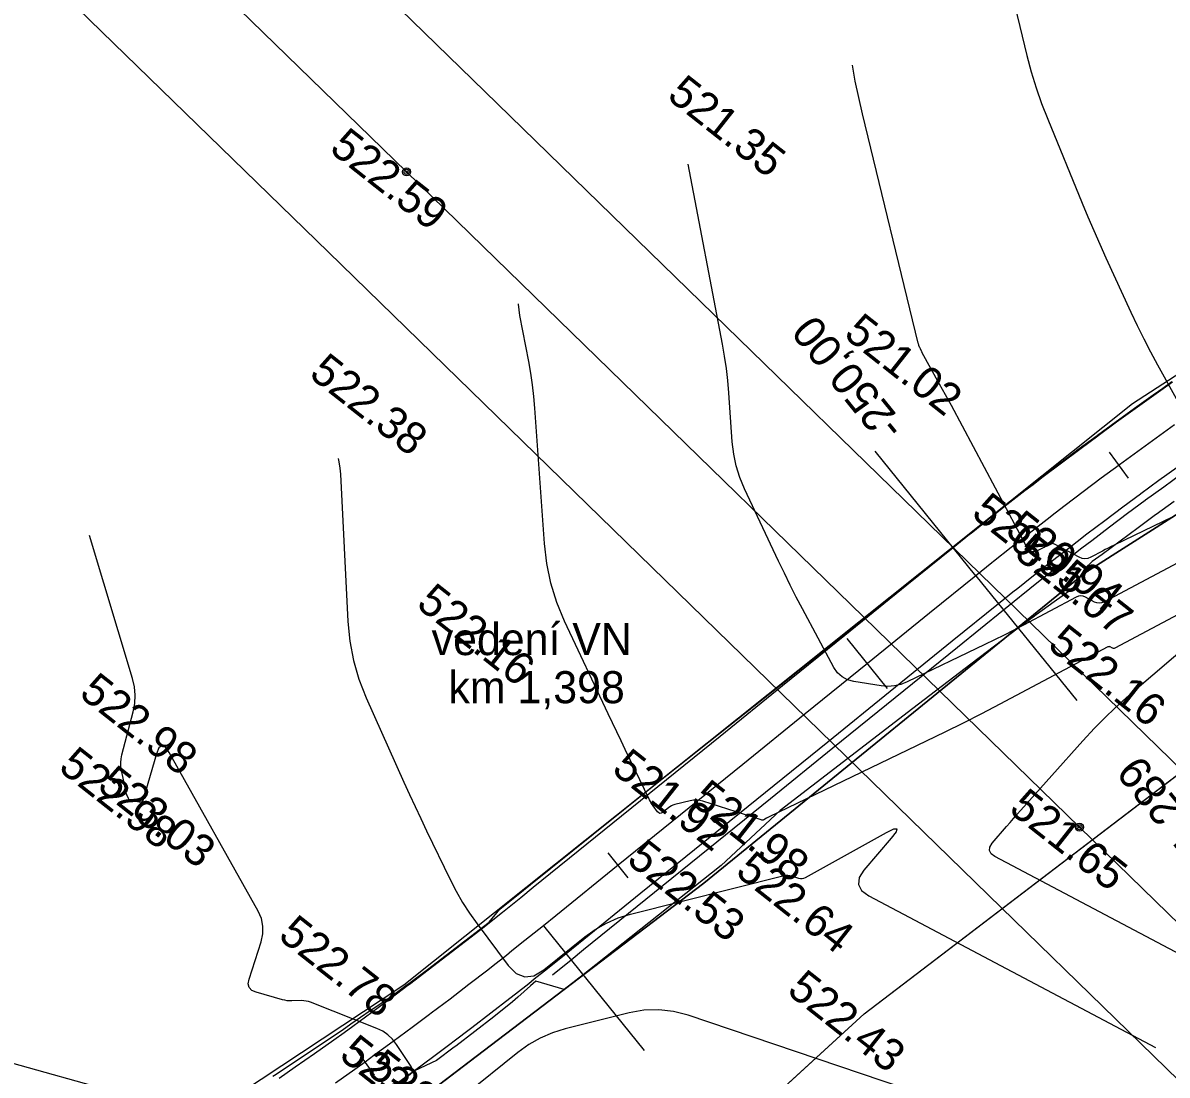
# Model space of a CAD drawing. Extents: x -636600 to -628587, y -1090963 to -1085869.
# Drawn here: x -629735.5 to -629664.1, y -1089734.5 to -1089668.9 of the extents above; entities that cross this region are included whole.
import ezdxf

# ---------------------------------------------------------------- set-up
doc = ezdxf.new("R2010")
doc.units = 0
for name, color, linetype in [('01_PARCELY_NÁVRH_PC', 7, 'Continuous'), ('07_OCH_P A POPISY TI', 7, 'Continuous'), ('21', 7, 'Continuous'), ('33', 7, 'Continuous'), ('34', 7, 'Continuous'), ('dno příkopu', 7, 'Continuous'), ('Ex_Major Contours', 7, 'Continuous'), ('Ex_Minor Contours', 7, 'Continuous'), ('HEKTOMETRY100', 7, 'Continuous'), ('HEKTOMETRY20', 7, 'Continuous'), ('HL_BODY', 7, 'Continuous'), ('koty_vše', 7, 'Continuous'), ('PARCELY_NÁVRH_SILNICE_ŽELEZNICE', 7, 'Continuous'), ('POLOMERY', 7, 'Continuous'), ('popis', 7, 'Continuous'), ('situace_osa', 7, 'Continuous'), ('situace_těleso', 7, 'Continuous'), ('situace_vozovka', 7, 'Continuous')]:
    doc.layers.add(name, color=color, linetype=linetype)

msp = doc.modelspace()

# ---------------------------------------------------------------- linework, layer by layer
at = {"layer": '01_PARCELY_NÁVRH_PC'}
msp.add_lwpolyline([(-629647.363, -1089680.417), (-629666.288, -1089692.668), (-629711.76, -1089728.929), (-629739.767, -1089747.431), (-629770.066, -1089766.37), (-629781.624, -1089778.209), (-629800.275, -1089807.802), (-629798.048, -1089809.483), (-629791.307, -1089814.356), (-629789.014, -1089815.993), (-629775.661, -1089789.328), (-629773.774, -1089778.258), (-629755.349, -1089764.02), (-629715.944, -1089740.02), (-629693.039, -1089722.565), (-629669.229, -1089703.189), (-629636.498, -1089682.368)], dxfattribs=at)
at = {"layer": '07_OCH_P A POPISY TI'}
for points in [[(-629808.416, -1089574.342), (-629758.17, -1089623.152), (-629706.697, -1089673.191), (-629664.708, -1089714.065), (-629606.854, -1089770.374), (-629556.972, -1089818.979), (-629519.085, -1089855.932)], [(-629812.884, -1089589.521), (-629767.926, -1089633.192), (-629716.459, -1089683.226), (-629674.473, -1089724.097), (-629616.621, -1089780.404), (-629566.745, -1089829.004), (-629539.136, -1089855.932)]]:
    msp.add_lwpolyline(points, dxfattribs=at)
at = {"layer": '21'}
for p, q in [((-629636.498, -1089682.368), (-629669.229, -1089703.189)), ((-629669.229, -1089703.189), (-629693.039, -1089722.565)), ((-629683.036, -1089730.713), (-629659.95, -1089713.109)), ((-629693.039, -1089722.565), (-629715.944, -1089740.02)), ((-629704.711, -1089750.564), (-629683.036, -1089730.713))]:
    msp.add_line(p, q, dxfattribs=at)
at = {"layer": '33'}
for centre, radius in [((-629711.578, -1089678.208), 0.25), ((-629711.578, -1089678.208), 0.158), ((-629711.578, -1089678.208), 0.05), ((-629669.591, -1089719.081), 0.25), ((-629669.591, -1089719.081), 0.158), ((-629669.591, -1089719.081), 0.05)]:
    msp.add_circle(centre, radius, dxfattribs=at)
at = {"layer": '34'}
for p, q in [((-629763.048, -1089628.172), (-629711.578, -1089678.208)), ((-629711.578, -1089678.208), (-629669.591, -1089719.081)), ((-629669.591, -1089719.081), (-629611.696, -1089775.422))]:
    msp.add_line(p, q, dxfattribs=at)
at = {"layer": 'dno příkopu'}
msp.add_lwpolyline([(-629663.207, -1089697.045), (-629664.34, -1089697.865), (-629665.469, -1089698.692), (-629665.493, -1089698.71), (-629666.593, -1089699.525), (-629667.713, -1089700.365), (-629668.828, -1089701.211), (-629669.444, -1089701.683), (-629669.938, -1089702.063), (-629671.043, -1089702.921), (-629672.143, -1089703.786), (-629673.238, -1089704.657), (-629673.335, -1089704.734), (-629674.329, -1089705.534), (-629677.213, -1089707.868), (-629681.101, -1089711.012), (-629684.988, -1089714.157), (-629688.875, -1089717.302), (-629692.762, -1089720.447), (-629696.649, -1089723.592), (-629700.536, -1089726.737), (-629701.31, -1089727.363), (-629702.477, -1089728.301)], dxfattribs=at)
at = {"layer": 'Ex_Major Contours'}
msp.add_lwpolyline([(-629715.841, -1089696.08), (-629715.797, -1089696.291), (-629715.742, -1089696.678), (-629715.711, -1089697.068), (-629715.247, -1089706.26), (-629715.129, -1089707.486), (-629714.899, -1089708.685), (-629714.559, -1089709.856), (-629714.107, -1089711.002), (-629711.745, -1089716.269), (-629711.401, -1089717.03), (-629711.051, -1089717.788), (-629710.696, -1089718.543), (-629710.335, -1089719.296), (-629708.858, -1089722.349), (-629708.49, -1089723.067), (-629708.088, -1089723.766), (-629707.653, -1089724.444), (-629707.186, -1089725.102), (-629705.25, -1089727.696), (-629704.748, -1089728.2), (-629704.209, -1089728.415), (-629703.633, -1089728.341), (-629703.021, -1089727.978), (-629700.465, -1089725.922), (-629699.81, -1089725.45), (-629699.115, -1089725.055), (-629698.382, -1089724.74), (-629697.609, -1089724.502), (-629688.012, -1089722.099), (-629687.9, -1089722.079), (-629687.787, -1089722.074), (-629687.675, -1089722.086), (-629687.564, -1089722.114), (-629687.12, -1089722.258), (-629687.01, -1089722.282), (-629686.903, -1089722.283), (-629686.797, -1089722.261), (-629686.694, -1089722.216), (-629681.626, -1089719.408), (-629681.179, -1089719.192), (-629680.981, -1089719.18), (-629681.032, -1089719.372), (-629681.334, -1089719.767), (-629683.04, -1089721.754), (-629683.341, -1089722.227), (-629683.39, -1089722.652), (-629683.188, -1089723.029), (-629682.735, -1089723.359), (-629664.849, -1089732.81)], dxfattribs=at)
at = {"layer": 'Ex_Minor Contours'}
for points in [[(-629674.115, -1089665.758), (-629673.921, -1089666.628), (-629672.869, -1089670.954), (-629672.603, -1089671.966), (-629672.299, -1089672.966), (-629671.956, -1089673.954), (-629671.576, -1089674.929), (-629669.424, -1089680.154), (-629669.066, -1089681.012), (-629668.699, -1089681.866), (-629668.324, -1089682.717), (-629667.941, -1089683.564), (-629666.385, -1089686.956), (-629665.993, -1089687.791), (-629665.584, -1089688.618), (-629665.159, -1089689.437), (-629664.719, -1089690.248), (-629662.183, -1089694.81)], [(-629650.979, -1089693.544), (-629667.431, -1089701.486), (-629667.616, -1089701.576), (-629667.799, -1089701.668), (-629667.982, -1089701.761), (-629668.164, -1089701.857), (-629668.89, -1089702.242), (-629669.071, -1089702.314), (-629669.252, -1089702.338), (-629669.434, -1089702.314), (-629669.615, -1089702.242), (-629671.154, -1089701.421), (-629671.212, -1089701.398), (-629671.27, -1089701.39), (-629671.328, -1089701.397), (-629671.386, -1089701.42), (-629671.619, -1089701.544), (-629671.677, -1089701.574), (-629671.736, -1089701.604), (-629671.795, -1089701.634), (-629671.854, -1089701.662), (-629672.326, -1089701.889), (-629672.365, -1089701.904), (-629672.404, -1089701.913), (-629672.444, -1089701.916), (-629672.485, -1089701.913), (-629672.65, -1089701.887), (-629672.689, -1089701.877), (-629672.722, -1089701.859), (-629672.75, -1089701.834), (-629672.773, -1089701.801), (-629677.589, -1089692.781), (-629677.769, -1089692.446), (-629677.95, -1089692.111), (-629678.133, -1089691.777), (-629678.318, -1089691.443), (-629679.4, -1089689.496), (-629679.414, -1089689.471), (-629679.427, -1089689.445), (-629679.44, -1089689.419), (-629679.452, -1089689.393), (-629679.5, -1089689.289), (-629679.512, -1089689.262), (-629679.523, -1089689.236), (-629679.535, -1089689.209), (-629679.546, -1089689.183), (-629679.609, -1089689.03), (-629679.623, -1089688.995), (-629679.635, -1089688.96), (-629679.646, -1089688.924), (-629679.655, -1089688.888), (-629683.132, -1089674.583), (-629683.582, -1089672.561), (-629683.765, -1089671.56)], [(-629656.845, -1089699.077), (-629668.072, -1089705.039), (-629668.216, -1089705.096), (-629668.36, -1089705.115), (-629668.504, -1089705.096), (-629668.647, -1089705.038), (-629669.222, -1089704.732), (-629669.366, -1089704.674), (-629669.51, -1089704.655), (-629669.653, -1089704.674), (-629669.797, -1089704.731), (-629673.092, -1089706.475), (-629673.691, -1089706.788), (-629674.292, -1089707.095), (-629674.897, -1089707.396), (-629675.504, -1089707.692), (-629680.348, -1089710.02), (-629680.74, -1089710.175), (-629681.142, -1089710.267), (-629681.553, -1089710.296), (-629681.973, -1089710.262), (-629683.673, -1089709.999), (-629684.07, -1089709.895), (-629684.411, -1089709.712), (-629684.697, -1089709.45), (-629684.927, -1089709.11), (-629686.875, -1089705.463), (-629687.262, -1089704.727), (-629687.64, -1089703.985), (-629688.009, -1089703.239), (-629688.368, -1089702.489), (-629690.498, -1089697.968), (-629690.79, -1089697.265), (-629691.015, -1089696.545), (-629691.171, -1089695.807), (-629691.259, -1089695.051), (-629691.474, -1089691.99), (-629691.539, -1089691.227), (-629691.627, -1089690.466), (-629691.737, -1089689.709), (-629691.87, -1089688.954), (-629694.019, -1089677.725)], [(-629658.821, -1089703.357), (-629667.397, -1089707.911), (-629667.433, -1089707.925), (-629667.468, -1089707.929), (-629667.503, -1089707.924), (-629667.538, -1089707.91), (-629667.679, -1089707.835), (-629667.714, -1089707.821), (-629667.749, -1089707.817), (-629667.784, -1089707.821), (-629667.819, -1089707.835), (-629674.565, -1089711.406), (-629675.704, -1089712.001), (-629676.848, -1089712.586), (-629677.998, -1089713.159), (-629679.154, -1089713.722), (-629688.954, -1089718.432), (-629688.997, -1089718.453), (-629689.039, -1089718.475), (-629689.082, -1089718.497), (-629689.124, -1089718.52), (-629689.291, -1089718.612), (-629689.333, -1089718.631), (-629689.376, -1089718.64), (-629689.42, -1089718.639), (-629689.465, -1089718.629), (-629693.089, -1089717.457), (-629693.285, -1089717.408), (-629693.481, -1089717.387), (-629693.679, -1089717.394), (-629693.877, -1089717.43), (-629694.849, -1089717.674), (-629694.957, -1089717.707), (-629695.059, -1089717.751), (-629695.156, -1089717.806), (-629695.247, -1089717.871), (-629695.603, -1089718.158), (-629695.689, -1089718.209), (-629695.769, -1089718.219), (-629695.844, -1089718.189), (-629695.914, -1089718.119), (-629696.184, -1089717.757), (-629696.249, -1089717.665), (-629696.31, -1089717.571), (-629696.366, -1089717.474), (-629696.417, -1089717.373), (-629697.933, -1089714.239), (-629698.201, -1089713.683), (-629698.468, -1089713.126), (-629698.733, -1089712.568), (-629698.997, -1089712.009), (-629701.722, -1089706.225), (-629702.207, -1089705.06), (-629702.579, -1089703.865), (-629702.838, -1089702.641), (-629702.984, -1089701.388), (-629703.579, -1089692.942), (-629703.641, -1089692.213), (-629703.724, -1089691.487), (-629703.83, -1089690.764), (-629703.956, -1089690.044), (-629704.507, -1089687.169), (-629704.599, -1089686.453), (-629704.599, -1089686.445)], [(-629711.09, -1089734.688), (-629711.128, -1089734.356), (-629711.294, -1089734.014), (-629712.208, -1089732.626), (-629712.457, -1089732.304), (-629712.745, -1089732.03), (-629713.072, -1089731.804), (-629713.439, -1089731.628), (-629717.568, -1089730), (-629717.707, -1089729.952), (-629717.849, -1089729.92), (-629717.993, -1089729.902), (-629718.14, -1089729.898), (-629718.732, -1089729.913), (-629718.879, -1089729.912), (-629719.025, -1089729.899), (-629719.17, -1089729.875), (-629719.313, -1089729.841), (-629720.965, -1089729.377), (-629721.234, -1089729.258), (-629721.397, -1089729.082), (-629721.454, -1089728.848), (-629721.405, -1089728.558), (-629720.653, -1089726.223), (-629720.546, -1089725.732), (-629720.541, -1089725.252), (-629720.641, -1089724.783), (-629720.843, -1089724.323), (-629726.388, -1089714.421), (-629726.631, -1089714.082), (-629726.846, -1089713.985), (-629727.033, -1089714.129), (-629727.193, -1089714.514), (-629728.007, -1089717.349), (-629728.045, -1089717.434), (-629728.101, -1089717.489), (-629728.176, -1089717.515), (-629728.269, -1089717.511), (-629728.762, -1089717.42), (-629728.818, -1089717.403), (-629728.865, -1089717.375), (-629728.903, -1089717.337), (-629728.932, -1089717.287), (-629729.032, -1089717.065), (-629729.056, -1089717.009), (-629729.076, -1089716.952), (-629729.093, -1089716.893), (-629729.107, -1089716.834), (-629729.375, -1089715.519), (-629729.41, -1089715.28), (-629729.417, -1089715.043), (-629729.396, -1089714.806), (-629729.348, -1089714.569), (-629728.635, -1089711.887), (-629728.533, -1089711.363), (-629728.505, -1089710.839), (-629728.551, -1089710.317), (-629728.672, -1089709.796), (-629731.374, -1089700.882)], [(-629663.269, -1089727.043), (-629674.878, -1089720.908), (-629675.114, -1089720.737), (-629675.219, -1089720.541), (-629675.193, -1089720.32), (-629675.037, -1089720.074), (-629674.15, -1089719.042), (-629673.928, -1089718.784), (-629673.704, -1089718.528), (-629673.48, -1089718.272), (-629673.253, -1089718.018), (-629669.383, -1089713.692), (-629668.65, -1089712.899), (-629667.891, -1089712.133), (-629667.107, -1089711.392), (-629666.298, -1089710.677), (-629658.42, -1089703.946)], [(-629672.444, -1089738.109), (-629694, -1089730.812), (-629694.917, -1089730.571), (-629695.839, -1089730.465), (-629696.767, -1089730.496), (-629697.7, -1089730.662), (-629701.681, -1089731.659), (-629702.479, -1089731.904), (-629703.236, -1089732.23), (-629703.953, -1089732.637), (-629704.63, -1089733.125), (-629707.951, -1089735.797)], [(-629736.748, -1089733.625), (-629729.613, -1089735.629)]]:
    msp.add_lwpolyline(points, dxfattribs=at)
at = {"layer": 'HEKTOMETRY100'}
msp.add_lwpolyline([(-629681.572, -1089710.429), (-629684.088, -1089707.32)], dxfattribs=at)
at = {"layer": 'HEKTOMETRY20'}
for points in [[(-629666.531, -1089697.301), (-629667.717, -1089695.691)], [(-629697.75, -1089722.231), (-629699.008, -1089720.676)], [(-629713.584, -1089734.535), (-629714.753, -1089732.912)]]:
    msp.add_lwpolyline(points, dxfattribs=at)
at = {"layer": 'HL_BODY'}
for points in [[(-629676.058, -1089703.396), (-629669.769, -1089711.17)], [(-629703.04, -1089725.225), (-629696.75, -1089732.999)]]:
    msp.add_lwpolyline(points, dxfattribs=at)
at = {"layer": 'PARCELY_NÁVRH_SILNICE_ŽELEZNICE'}
msp.add_lwpolyline([(-629636.498, -1089682.368), (-629669.229, -1089703.189), (-629693.039, -1089722.565), (-629715.944, -1089740.02), (-629755.349, -1089764.02), (-629773.774, -1089778.258), (-629775.661, -1089789.328), (-629789.014, -1089815.993), (-629763.271, -1089834.375), (-629762.496, -1089834.892), (-629746.798, -1089807.362), (-629739.641, -1089797.354), (-629724.72, -1089773.793), (-629704.711, -1089750.564), (-629683.036, -1089730.713), (-629659.95, -1089713.109)], dxfattribs=at)
at = {"layer": 'POLOMERY'}
for points in [[(-629676.058, -1089703.396), (-629682.348, -1089695.621)], [(-629703.04, -1089725.225), (-629696.75, -1089732.999)]]:
    msp.add_lwpolyline(points, dxfattribs=at)
at = {"layer": 'situace_osa'}
msp.add_lwpolyline([(-629663.662, -1089693.99), (-629664.812, -1089694.813), (-629665.959, -1089695.642), (-629667.1, -1089696.478), (-629667.124, -1089696.496), (-629668.237, -1089697.32), (-629669.369, -1089698.169), (-629670.496, -1089699.025), (-629671.119, -1089699.502), (-629671.618, -1089699.886), (-629672.736, -1089700.754), (-629673.848, -1089701.628), (-629674.956, -1089702.509), (-629675.054, -1089702.587), (-629676.058, -1089703.396), (-629678.943, -1089705.73), (-629682.83, -1089708.874), (-629686.717, -1089712.019), (-629690.605, -1089715.164), (-629694.492, -1089718.309), (-629698.379, -1089721.454), (-629702.266, -1089724.599), (-629703.04, -1089725.225), (-629704.194, -1089726.152), (-629705.006, -1089726.799), (-629705.353, -1089727.073), (-629706.173, -1089727.718), (-629706.518, -1089727.987), (-629707.688, -1089728.894), (-629708.863, -1089729.795), (-629710.044, -1089730.688), (-629710.141, -1089730.761), (-629711.23, -1089731.574), (-629712.421, -1089732.453), (-629713.617, -1089733.325), (-629714.169, -1089733.724), (-629714.819, -1089734.19), (-629716.025, -1089735.048)], dxfattribs=at)
at = {"layer": 'situace_těleso'}
for points in [[(-629719.926, -1089734.605), (-629719.725, -1089734.475), (-629718.699, -1089733.802), (-629717.478, -1089732.992), (-629716.261, -1089732.174), (-629715.606, -1089731.728), (-629715.049, -1089731.348), (-629713.842, -1089730.515), (-629712.621, -1089729.701), (-629711.54, -1089728.898), (-629711.443, -1089728.826), (-629710.27, -1089727.946), (-629709.102, -1089727.059), (-629707.939, -1089726.165), (-629707.597, -1089725.9), (-629706.781, -1089725.264), (-629706.436, -1089724.994), (-629705.769, -1089724.182), (-629704.623, -1089723.268), (-629703.847, -1089722.645), (-629699.948, -1089719.514), (-629696.041, -1089716.394), (-629692.128, -1089713.281), (-629688.21, -1089710.175), (-629684.292, -1089707.068), (-629680.374, -1089703.961), (-629677.481, -1089701.637), (-629676.475, -1089700.812), (-629676.377, -1089700.732), (-629675.268, -1089699.833), (-629674.153, -1089698.94), (-629673.031, -1089698.057), (-629672.527, -1089697.67), (-629671.897, -1089697.189), (-629670.759, -1089696.326), (-629669.616, -1089695.471), (-629668.492, -1089694.64), (-629668.468, -1089694.622), (-629667.315, -1089693.779), (-629666.157, -1089692.943), (-629664.995, -1089692.114), (-629664.397, -1089691.691), (-629663.828, -1089691.291)], [(-629663.689, -1089698.76), (-629664.817, -1089699.577), (-629664.841, -1089699.594), (-629665.938, -1089700.405), (-629667.05, -1089701.243), (-629668.177, -1089702.063), (-629668.807, -1089702.512), (-629669.25, -1089702.953), (-629670.04, -1089704.205), (-629671.171, -1089705.016), (-629672.295, -1089705.836), (-629672.395, -1089705.909), (-629673.414, -1089706.664), (-629676.368, -1089708.912), (-629680.338, -1089711.955), (-629684.308, -1089714.998), (-629688.277, -1089718.041), (-629691.941, -1089721.461), (-629695.86, -1089724.567), (-629699.779, -1089727.673), (-629700.559, -1089728.291), (-629701.749, -1089729.211), (-629703.516, -1089728.679), (-629703.849, -1089728.978), (-629704.638, -1089729.68), (-629704.968, -1089729.973), (-629706.132, -1089730.913), (-629707.317, -1089731.825), (-629708.508, -1089732.73), (-629708.606, -1089732.804), (-629709.705, -1089733.627), (-629711.077, -1089734.285), (-629712.239, -1089735.228)]]:
    msp.add_lwpolyline(points, dxfattribs=at)
at = {"layer": 'situace_vozovka'}
for points in [[(-629663.799, -1089691.332), (-629664.368, -1089691.732), (-629664.965, -1089692.156), (-629666.126, -1089692.986), (-629667.283, -1089693.823), (-629668.435, -1089694.667), (-629668.459, -1089694.684), (-629669.582, -1089695.517), (-629670.724, -1089696.373), (-629671.861, -1089697.236), (-629672.49, -1089697.718), (-629672.994, -1089698.105), (-629674.121, -1089698.981), (-629675.244, -1089699.863), (-629676.361, -1089700.752), (-629676.46, -1089700.831), (-629677.473, -1089701.647), (-629680.358, -1089703.98), (-629684.245, -1089707.125), (-629688.133, -1089710.27), (-629692.02, -1089713.415), (-629695.907, -1089716.56), (-629699.794, -1089719.705), (-629703.681, -1089722.849), (-629704.455, -1089723.476), (-629705.599, -1089724.395), (-629706.404, -1089725.036), (-629706.747, -1089725.307), (-629707.56, -1089725.947), (-629707.901, -1089726.213), (-629709.061, -1089727.112), (-629710.226, -1089728.004), (-629711.396, -1089728.889), (-629711.492, -1089728.962), (-629712.571, -1089729.768), (-629713.751, -1089730.639), (-629714.937, -1089731.503), (-629715.484, -1089731.898), (-629716.128, -1089732.36), (-629717.323, -1089733.21), (-629718.524, -1089734.053), (-629719.533, -1089734.753)], [(-629663.799, -1089691.332), (-629664.368, -1089691.732), (-629664.965, -1089692.156), (-629666.126, -1089692.986), (-629667.283, -1089693.823), (-629668.435, -1089694.667), (-629668.459, -1089694.684), (-629669.582, -1089695.517), (-629670.724, -1089696.373), (-629671.861, -1089697.236), (-629672.49, -1089697.718), (-629672.994, -1089698.105), (-629674.121, -1089698.981), (-629675.244, -1089699.863), (-629676.361, -1089700.752), (-629676.46, -1089700.831), (-629677.473, -1089701.647), (-629680.358, -1089703.98), (-629684.245, -1089707.125), (-629688.133, -1089710.27), (-629692.02, -1089713.415), (-629695.907, -1089716.56), (-629699.794, -1089719.705), (-629703.681, -1089722.849), (-629704.455, -1089723.476), (-629705.599, -1089724.395), (-629706.404, -1089725.036), (-629706.747, -1089725.307), (-629707.56, -1089725.947), (-629707.901, -1089726.213), (-629709.061, -1089727.112), (-629710.226, -1089728.004), (-629711.396, -1089728.889), (-629711.492, -1089728.962), (-629712.571, -1089729.768), (-629713.751, -1089730.639), (-629714.937, -1089731.503), (-629715.484, -1089731.898), (-629716.128, -1089732.36), (-629717.323, -1089733.21), (-629718.524, -1089734.053), (-629719.533, -1089734.753)], [(-629663.499, -1089696.639), (-629664.634, -1089697.461), (-629665.766, -1089698.29), (-629665.789, -1089698.307), (-629666.892, -1089699.124), (-629668.014, -1089699.966), (-629669.131, -1089700.813), (-629669.749, -1089701.286), (-629670.243, -1089701.667), (-629671.351, -1089702.527), (-629672.453, -1089703.394), (-629673.55, -1089704.266), (-629673.648, -1089704.344), (-629674.643, -1089705.145), (-629677.528, -1089707.479), (-629681.415, -1089710.624), (-629685.302, -1089713.769), (-629689.189, -1089716.913), (-629693.077, -1089720.058), (-629696.964, -1089723.203), (-629700.851, -1089726.348), (-629701.625, -1089726.974), (-629702.789, -1089727.91), (-629703.609, -1089728.562), (-629703.959, -1089728.839), (-629704.786, -1089729.49), (-629705.134, -1089729.761), (-629706.314, -1089730.677), (-629707.5, -1089731.585), (-629708.691, -1089732.486), (-629708.79, -1089732.56), (-629709.888, -1089733.38), (-629711.09, -1089734.267), (-629712.297, -1089735.147)], [(-629663.499, -1089696.639), (-629664.634, -1089697.461), (-629665.766, -1089698.29), (-629665.789, -1089698.307), (-629666.892, -1089699.124), (-629668.014, -1089699.966), (-629669.131, -1089700.813), (-629669.749, -1089701.286), (-629670.243, -1089701.667), (-629671.351, -1089702.527), (-629672.453, -1089703.394), (-629673.55, -1089704.266), (-629673.648, -1089704.344), (-629674.643, -1089705.145), (-629677.528, -1089707.479), (-629681.415, -1089710.624), (-629685.302, -1089713.769), (-629689.189, -1089716.913), (-629693.077, -1089720.058), (-629696.964, -1089723.203), (-629700.851, -1089726.348), (-629701.625, -1089726.974), (-629702.789, -1089727.91), (-629703.609, -1089728.562), (-629703.959, -1089728.839), (-629704.786, -1089729.49), (-629705.134, -1089729.761), (-629706.314, -1089730.677), (-629707.5, -1089731.585), (-629708.691, -1089732.486), (-629708.79, -1089732.56), (-629709.888, -1089733.38), (-629711.09, -1089734.267), (-629712.297, -1089735.147)]]:
    msp.add_lwpolyline(points, dxfattribs=at)

# ---------------------------------------------------------------- texts
at = {"layer": 'HL_BODY'}
msp.add_text('KT1+391,289', height=2, rotation=128.97371, dxfattribs=at).set_placement((-629655.67, -1089727.007))
at = {"layer": 'koty_vše'}
for s, p in [('521.35', (-629695.403, -1089673.596)), ('522.59', (-629716.47, -1089676.896)), ('521.02', (-629684.377, -1089688.46)), ('522.38', (-629717.74, -1089690.95)), ('520.95', (-629676.419, -1089699.644)), ('520.94', (-629674.317, -1089700.742)), ('521.07', (-629673.738, -1089702.179)), ('522.16', (-629711.049, -1089705.299)), ('522.16', (-629671.665, -1089707.852)), ('522.98', (-629732.085, -1089710.878)), ('522.98', (-629733.378, -1089715.487)), ('521.92', (-629698.856, -1089715.607)), ('523.03', (-629730.961, -1089716.656)), ('521.98', (-629693.928, -1089717.546)), ('521.65', (-629674.075, -1089718.091)), ('522.53', (-629697.925, -1089721.258)), ('522.64', (-629691.141, -1089722)), ('522.78', (-629719.667, -1089725.987)), ('522.43', (-629687.922, -1089729.406)), ('523.11', (-629715.866, -1089733.444)), ('522.81', (-629714.17, -1089734.35))]:
    msp.add_text(s, height=2, rotation=321.72649, dxfattribs=at).set_placement(p)
at = {"layer": 'POLOMERY'}
msp.add_text('-250,00', height=2, rotation=128.97371, dxfattribs=at).set_placement((-629680.404, -1089694.049))
at = {"layer": 'popis'}
for s, p in [('vedení VN', (-629710.014, -1089708.347)), ('km 1,398', (-629708.967, -1089711.347))]:
    msp.add_text(s, height=2, dxfattribs=at).set_placement(p)

doc.saveas('drawing.dxf')
